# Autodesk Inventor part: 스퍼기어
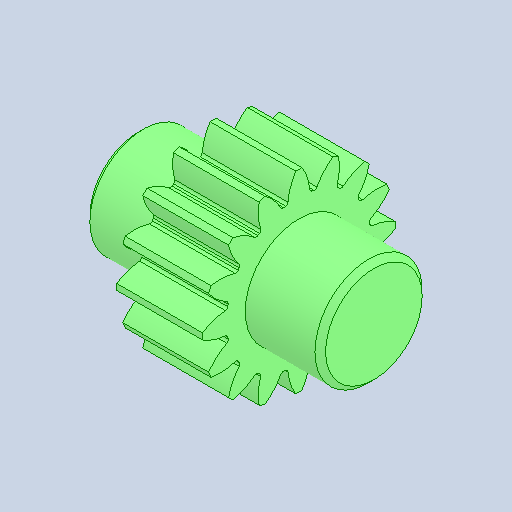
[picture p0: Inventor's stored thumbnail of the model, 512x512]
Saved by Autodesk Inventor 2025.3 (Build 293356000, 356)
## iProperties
Created: 2025-10
Part Number: 스퍼기어
Material: 강철, 합금
Document SubType Name: Modeling
Designer: PC-15
Density: 7.73 g/cm^3
Appearance: 기본값
Author: jhkim
Sending System: Autodesk Inventor 2026
Preprocessor: ST-DEVELOPER v20.1
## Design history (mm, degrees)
feature "솔리드1"
node "솔리드2"
